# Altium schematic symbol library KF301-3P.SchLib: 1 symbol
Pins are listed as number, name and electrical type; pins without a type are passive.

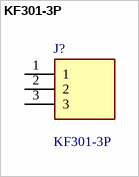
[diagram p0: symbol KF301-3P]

## KF301-3P
designator J?
Terminal Block 5mm Pitch 3 Poles; Manufacturer_Name: Handson Technology; Geometry.Height: 10mm
footprint KF3013P
pins: 1, 2, 3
